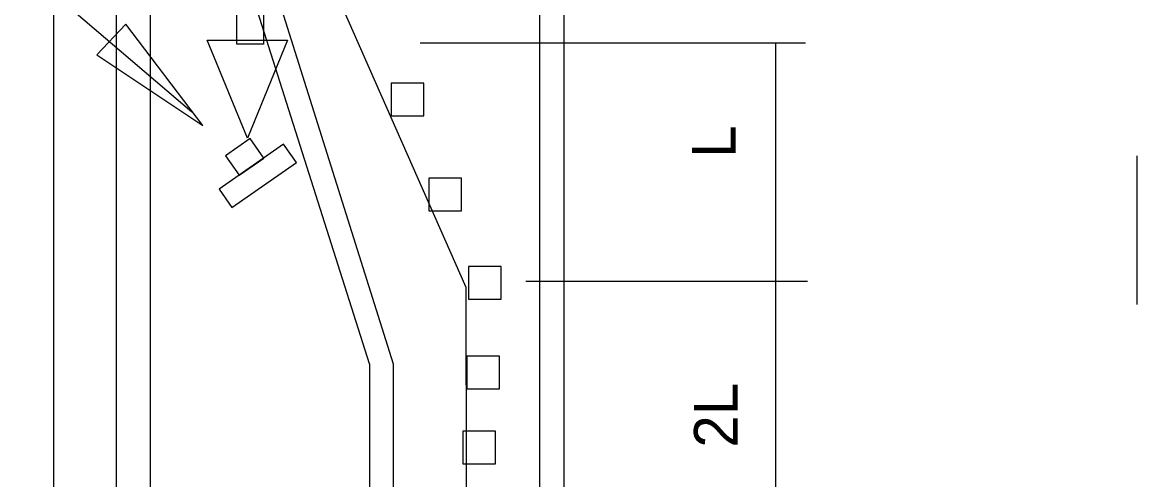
# Model space of a CAD drawing. Extents: x 1531.42 to 1538.58, y 1529.59 to 1539.57.
# Drawn here: x 1534.782 to 1536.313, y 1534.134 to 1534.762 of the extents above; entities that cross this region are included whole.
import ezdxf

# ---------------------------------------------------------------- set-up
doc = ezdxf.new("R2010")
doc.units = 0
for name, color, linetype in [('DETL-DIMS', 7, 'Continuous'), ('DETL-LINE', 7, 'Continuous'), ('DETL-NOTE', 7, 'Continuous')]:
    doc.layers.add(name, color=color, linetype=linetype)

msp = doc.modelspace()

# ---------------------------------------------------------------- linework, layer by layer
at = {"layer": 'DETL-DIMS'}
for p, q in [((1534.5927, 1535.0002), (1535.0146, 1534.6391)), ((1535.3282, 1534.7342), (1535.8575, 1534.7342)), ((1535.817, 1531.8557), (1535.817, 1534.7342)), ((1535.4735, 1534.4065), (1535.8602, 1534.4065))]:
    msp.add_line(p, q, dxfattribs=at)
msp.add_lwpolyline([(1534.9239, 1534.7597), (1534.8842, 1534.7175), (1535.0296, 1534.6205)], close=True, dxfattribs=at)
at = {"layer": 'DETL-LINE'}
for p, q in [((1534.8446, 1535.7136), (1535.2912, 1534.2929)), ((1534.8244, 1535.4758), (1534.8244, 1531.7535)), ((1535.492, 1535.4185), (1535.492, 1533.7389)), ((1535.5255, 1535.4185), (1535.5255, 1531.7597)), ((1534.9107, 1535.3085), (1534.9107, 1531.7597)), ((1534.9574, 1535.2406), (1534.9574, 1531.7597)), ((1535.2586, 1534.2929), (1535.093, 1534.8143)), ((1535.3916, 1534.3977), (1535.2102, 1534.8091)), ((1536.3126, 1534.5786), (1536.3126, 1534.3745)), ((1535.3916, 1534.2638), (1535.3916, 1534.3977)), ((1535.2586, 1534.2929), (1535.2586, 1531.7597)), ((1535.2912, 1534.2929), (1535.2912, 1531.7597)), ((1535.3916, 1534.2638), (1535.3916, 1534.0586))]:
    msp.add_line(p, q, dxfattribs=at)
for points in [[(1535.0763, 1534.8654), (1535.1124, 1534.8619), (1535.1132, 1534.7324), (1535.0763, 1534.7324)], [(1535.0358, 1534.7377), (1535.1458, 1534.7377), (1535.0912, 1534.6029)], [(1535.2883, 1534.6338), (1535.3331, 1534.6338), (1535.3331, 1534.6786), (1535.2883, 1534.6786)], [(1535.052, 1534.5329), (1535.0697, 1534.5076), (1535.1584, 1534.5697), (1535.1406, 1534.5949)], [(1535.0795, 1534.5521), (1535.1134, 1534.5758), (1535.0946, 1534.6027), (1535.0607, 1534.579)], [(1535.3403, 1534.5034), (1535.3851, 1534.5034), (1535.3851, 1534.5482), (1535.3403, 1534.5482)], [(1535.3946, 1534.382), (1535.4394, 1534.382), (1535.4394, 1534.4268), (1535.3946, 1534.4268)], [(1535.3922, 1534.2585), (1535.437, 1534.2585), (1535.437, 1534.3033), (1535.3922, 1534.3033)], [(1535.387, 1534.1555), (1535.4318, 1534.1555), (1535.4318, 1534.2003), (1535.387, 1534.2003)]]:
    msp.add_lwpolyline(points, close=True, dxfattribs=at)
msp.add_lwpolyline([(1534.8244, 1534.5258), (1534.8244, 1534.4258)], dxfattribs=at)

# ---------------------------------------------------------------- texts
at = {"layer": 'DETL-NOTE'}
for s, p in [('L', (1535.7615, 1534.5759)), ('2L', (1535.7644, 1534.1776))]:
    msp.add_text(s, height=0.06, rotation=90, dxfattribs=at).set_placement(p)

doc.saveas('drawing.dxf')
